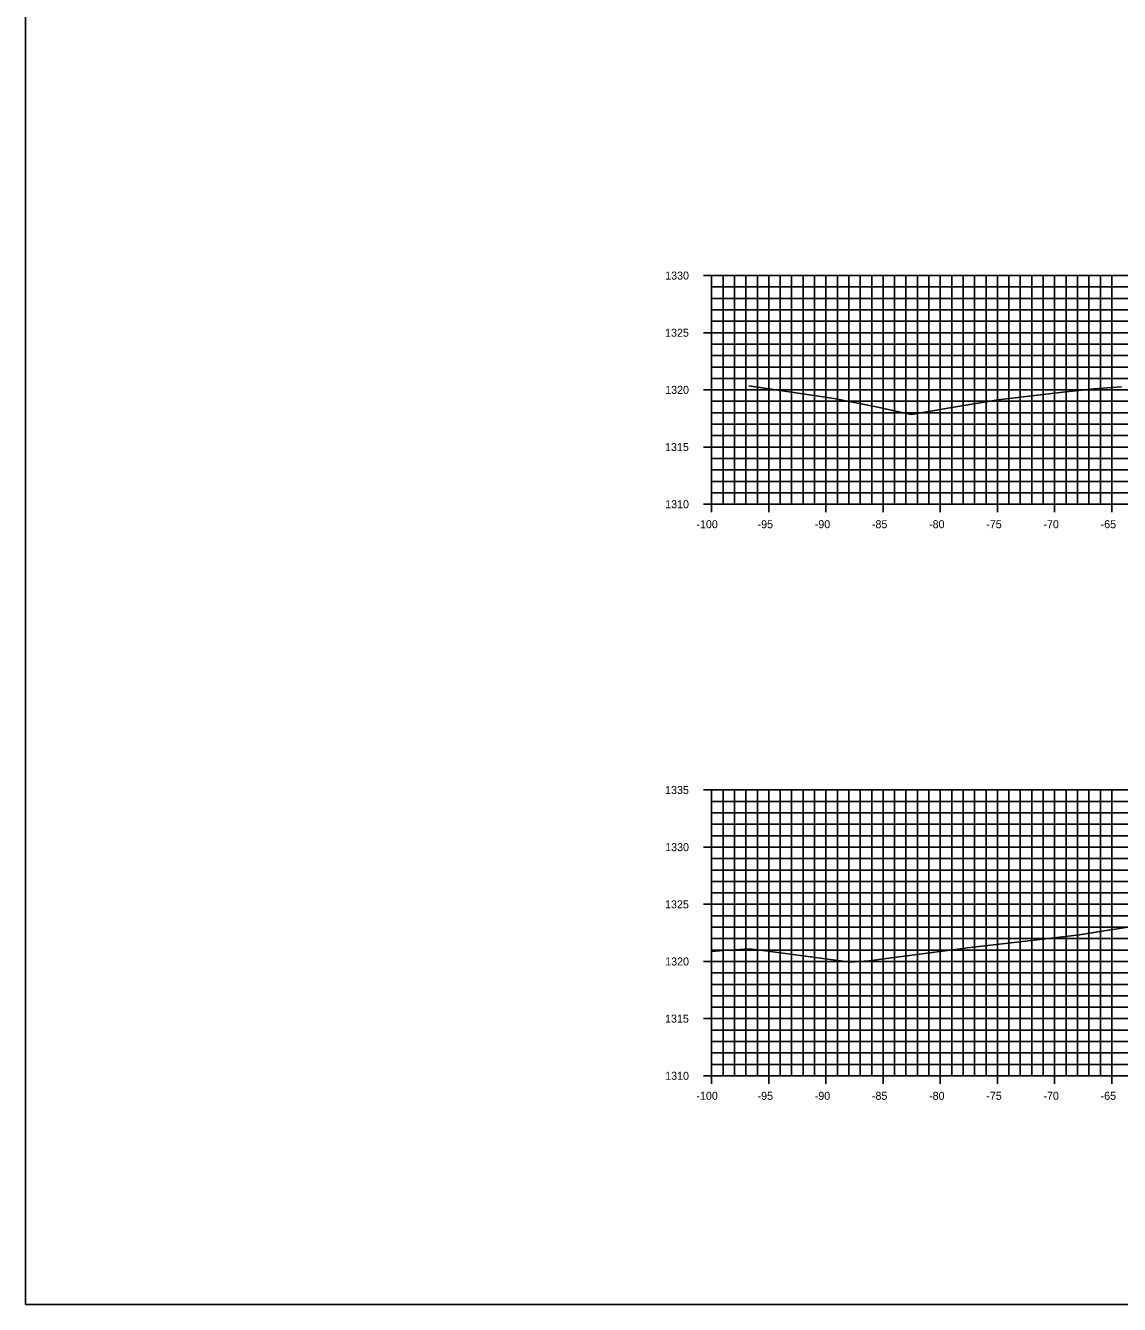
# Model space of a CAD drawing. Extents: x 674939 to 678919, y 750652 to 765176.
# Drawn here: x 678578.5 to 678674.2, y 753452.6 to 753564.4 of the extents above; entities that cross this region are included whole.
import ezdxf

# ---------------------------------------------------------------- set-up
doc = ezdxf.new("R2010")
doc.units = 0
for name, color, linetype in [('Level 10', 7, 'Continuous'), ('Level 20', 7, 'Continuous'), ('Level 4', 7, 'Continuous'), ('Level 8', 7, 'Continuous'), ('Level 9', 7, 'Continuous')]:
    doc.layers.add(name, color=color, linetype=linetype)

msp = doc.modelspace()

# ---------------------------------------------------------------- linework, layer by layer
at = {"layer": 'Level 10'}
for points in [[(678641.8, 753532.89), (678645.11, 753532.41), (678649.24, 753531.79), (678652.91, 753531.07), (678655.97, 753530.4), (678659.53, 753531.01), (678663.59, 753531.69), (678669.25, 753532.35), (678670.65, 753532.51), (678671.95, 753532.63), (678674.38, 753532.83)], [(678638.53, 753483.43), (678639.56, 753483.51), (678640.2, 753483.55), (678641.78, 753483.67), (678643.23, 753483.47), (678650.67, 753482.49), (678651.05, 753482.51), (678652.29, 753482.6), (678658.5, 753483.42), (678659.85, 753483.6), (678660.9, 753483.73), (678668, 753484.57), (678670.7, 753484.89), (678672.65, 753485.19), (678674.96, 753485.54)]]:
    msp.add_lwpolyline(points, dxfattribs=at)
at = {"layer": 'Level 20'}
for p, q in [((678638.53, 753542.55), (678838.53, 753542.55)), ((678638.53, 753522.55), (678638.53, 753542.55)), ((678639.53, 753522.55), (678639.53, 753542.55)), ((678640.53, 753522.55), (678640.53, 753542.55)), ((678641.53, 753522.55), (678641.53, 753542.55)), ((678642.53, 753522.55), (678642.53, 753542.55)), ((678643.53, 753522.55), (678643.53, 753542.55)), ((678644.53, 753522.55), (678644.53, 753542.55)), ((678645.53, 753522.55), (678645.53, 753542.55)), ((678646.53, 753522.55), (678646.53, 753542.55)), ((678647.53, 753522.55), (678647.53, 753542.55)), ((678648.53, 753522.55), (678648.53, 753542.55)), ((678649.53, 753522.55), (678649.53, 753542.55)), ((678650.53, 753522.55), (678650.53, 753542.55)), ((678651.53, 753522.55), (678651.53, 753542.55)), ((678652.53, 753522.55), (678652.53, 753542.55)), ((678653.53, 753522.55), (678653.53, 753542.55)), ((678654.53, 753522.55), (678654.53, 753542.55)), ((678655.53, 753522.55), (678655.53, 753542.55)), ((678656.53, 753522.55), (678656.53, 753542.55)), ((678657.53, 753522.55), (678657.53, 753542.55)), ((678658.53, 753522.55), (678658.53, 753542.55)), ((678659.53, 753522.55), (678659.53, 753542.55)), ((678660.53, 753522.55), (678660.53, 753542.55)), ((678661.53, 753522.55), (678661.53, 753542.55)), ((678662.53, 753522.55), (678662.53, 753542.55)), ((678663.53, 753522.55), (678663.53, 753542.55)), ((678664.53, 753522.55), (678664.53, 753542.55)), ((678665.53, 753522.55), (678665.53, 753542.55)), ((678666.53, 753522.55), (678666.53, 753542.55)), ((678667.53, 753522.55), (678667.53, 753542.55)), ((678668.53, 753522.55), (678668.53, 753542.55)), ((678669.53, 753522.55), (678669.53, 753542.55)), ((678670.53, 753522.55), (678670.53, 753542.55)), ((678671.53, 753522.55), (678671.53, 753542.55)), ((678672.53, 753522.55), (678672.53, 753542.55)), ((678673.53, 753522.55), (678673.53, 753542.55)), ((678638.53, 753541.55), (678838.53, 753541.55)), ((678638.53, 753540.55), (678838.53, 753540.55)), ((678638.53, 753539.55), (678838.53, 753539.55)), ((678638.53, 753538.55), (678838.53, 753538.55)), ((678638.53, 753537.55), (678838.53, 753537.55)), ((678638.53, 753536.55), (678838.53, 753536.55)), ((678638.53, 753535.55), (678838.53, 753535.55)), ((678638.53, 753534.55), (678838.53, 753534.55)), ((678638.53, 753533.55), (678838.53, 753533.55)), ((678638.53, 753532.55), (678838.53, 753532.55)), ((678638.53, 753531.55), (678838.53, 753531.55)), ((678638.53, 753530.55), (678838.53, 753530.55)), ((678638.53, 753529.55), (678838.53, 753529.55)), ((678638.53, 753528.55), (678838.53, 753528.55)), ((678638.53, 753527.55), (678838.53, 753527.55)), ((678638.53, 753526.55), (678838.53, 753526.55)), ((678638.53, 753525.55), (678838.53, 753525.55)), ((678638.53, 753524.55), (678838.53, 753524.55)), ((678638.53, 753523.55), (678838.53, 753523.55)), ((678638.53, 753522.55), (678838.53, 753522.55)), ((678638.53, 753497.55), (678838.53, 753497.55)), ((678638.53, 753472.55), (678638.53, 753497.55)), ((678639.53, 753472.55), (678639.53, 753497.55)), ((678640.53, 753472.55), (678640.53, 753497.55)), ((678641.53, 753472.55), (678641.53, 753497.55)), ((678642.53, 753472.55), (678642.53, 753497.55)), ((678643.53, 753472.55), (678643.53, 753497.55)), ((678644.53, 753472.55), (678644.53, 753497.55)), ((678645.53, 753472.55), (678645.53, 753497.55)), ((678646.53, 753472.55), (678646.53, 753497.55)), ((678647.53, 753472.55), (678647.53, 753497.55)), ((678648.53, 753472.55), (678648.53, 753497.55)), ((678649.53, 753472.55), (678649.53, 753497.55)), ((678650.53, 753472.55), (678650.53, 753497.55)), ((678651.53, 753472.55), (678651.53, 753497.55)), ((678652.53, 753472.55), (678652.53, 753497.55)), ((678653.53, 753472.55), (678653.53, 753497.55)), ((678654.53, 753472.55), (678654.53, 753497.55)), ((678655.53, 753472.55), (678655.53, 753497.55)), ((678656.53, 753472.55), (678656.53, 753497.55)), ((678657.53, 753472.55), (678657.53, 753497.55)), ((678658.53, 753472.55), (678658.53, 753497.55)), ((678659.53, 753472.55), (678659.53, 753497.55)), ((678660.53, 753472.55), (678660.53, 753497.55)), ((678661.53, 753472.55), (678661.53, 753497.55)), ((678662.53, 753472.55), (678662.53, 753497.55)), ((678663.53, 753472.55), (678663.53, 753497.55)), ((678664.53, 753472.55), (678664.53, 753497.55)), ((678665.53, 753472.55), (678665.53, 753497.55)), ((678666.53, 753472.55), (678666.53, 753497.55)), ((678667.53, 753472.55), (678667.53, 753497.55)), ((678668.53, 753472.55), (678668.53, 753497.55)), ((678669.53, 753472.55), (678669.53, 753497.55)), ((678670.53, 753472.55), (678670.53, 753497.55)), ((678671.53, 753472.55), (678671.53, 753497.55)), ((678672.53, 753472.55), (678672.53, 753497.55)), ((678673.53, 753472.55), (678673.53, 753497.55)), ((678638.53, 753496.55), (678838.53, 753496.55)), ((678638.53, 753495.55), (678838.53, 753495.55)), ((678638.53, 753494.55), (678838.53, 753494.55)), ((678638.53, 753493.55), (678838.53, 753493.55)), ((678638.53, 753492.55), (678838.53, 753492.55)), ((678638.53, 753491.55), (678838.53, 753491.55)), ((678638.53, 753490.55), (678838.53, 753490.55)), ((678638.53, 753489.55), (678838.53, 753489.55)), ((678638.53, 753488.55), (678838.53, 753488.55)), ((678638.53, 753487.55), (678838.53, 753487.55)), ((678638.53, 753486.55), (678838.53, 753486.55)), ((678638.53, 753485.55), (678838.53, 753485.55)), ((678638.53, 753484.55), (678838.53, 753484.55)), ((678638.53, 753483.55), (678838.53, 753483.55)), ((678638.53, 753482.55), (678838.53, 753482.55)), ((678638.53, 753481.55), (678838.53, 753481.55)), ((678638.53, 753480.55), (678838.53, 753480.55)), ((678638.53, 753479.55), (678838.53, 753479.55)), ((678638.53, 753478.55), (678838.53, 753478.55)), ((678638.53, 753477.55), (678838.53, 753477.55)), ((678638.53, 753476.55), (678838.53, 753476.55)), ((678638.53, 753475.55), (678838.53, 753475.55)), ((678638.53, 753474.55), (678838.53, 753474.55)), ((678638.53, 753473.55), (678838.53, 753473.55)), ((678638.53, 753472.55), (678838.53, 753472.55))]:
    msp.add_line(p, q, dxfattribs=at)
at = {"layer": 'Level 4'}
msp.add_lwpolyline([(678578.53, 753452.55), (678918.53, 753452.55), (678918.53, 753672.55), (678578.53, 753672.55)], close=True, dxfattribs=at)
at = {"layer": 'Level 8'}
for p, q in [((678637.83, 753542.55), (678639.23, 753542.55)), ((678638.53, 753522.55), (678638.53, 753542.55)), ((678638.53, 753541.55), (678638.88, 753541.55)), ((678638.53, 753540.55), (678638.88, 753540.55)), ((678638.53, 753539.55), (678638.88, 753539.55)), ((678638.53, 753538.55), (678638.88, 753538.55)), ((678637.83, 753537.55), (678639.23, 753537.55)), ((678638.53, 753536.55), (678638.88, 753536.55)), ((678638.53, 753535.55), (678638.88, 753535.55)), ((678638.53, 753534.55), (678638.88, 753534.55)), ((678638.53, 753533.55), (678638.88, 753533.55)), ((678637.83, 753532.55), (678639.23, 753532.55)), ((678638.53, 753531.55), (678638.88, 753531.55)), ((678638.53, 753530.55), (678638.88, 753530.55)), ((678638.53, 753529.55), (678638.88, 753529.55)), ((678638.53, 753528.55), (678638.88, 753528.55)), ((678637.83, 753527.55), (678639.23, 753527.55)), ((678638.53, 753526.55), (678638.88, 753526.55)), ((678638.53, 753525.55), (678638.88, 753525.55)), ((678638.53, 753524.55), (678638.88, 753524.55)), ((678638.53, 753523.55), (678638.88, 753523.55)), ((678638.53, 753521.85), (678638.53, 753523.25)), ((678643.53, 753521.85), (678643.53, 753523.25)), ((678648.53, 753521.85), (678648.53, 753523.25)), ((678653.53, 753521.85), (678653.53, 753523.25)), ((678658.53, 753521.85), (678658.53, 753523.25)), ((678663.53, 753521.85), (678663.53, 753523.25)), ((678668.53, 753521.85), (678668.53, 753523.25)), ((678673.53, 753521.85), (678673.53, 753523.25)), ((678637.83, 753522.55), (678639.23, 753522.55)), ((678638.53, 753522.55), (678838.53, 753522.55)), ((678637.83, 753497.55), (678639.23, 753497.55)), ((678638.53, 753472.55), (678638.53, 753497.55)), ((678638.53, 753496.55), (678638.88, 753496.55)), ((678638.53, 753495.55), (678638.88, 753495.55)), ((678638.53, 753494.55), (678638.88, 753494.55)), ((678638.53, 753493.55), (678638.88, 753493.55)), ((678637.83, 753492.55), (678639.23, 753492.55)), ((678638.53, 753491.55), (678638.88, 753491.55)), ((678638.53, 753490.55), (678638.88, 753490.55)), ((678638.53, 753489.55), (678638.88, 753489.55)), ((678638.53, 753488.55), (678638.88, 753488.55)), ((678637.83, 753487.55), (678639.23, 753487.55)), ((678638.53, 753486.55), (678638.88, 753486.55)), ((678638.53, 753485.55), (678638.88, 753485.55)), ((678638.53, 753484.55), (678638.88, 753484.55)), ((678637.83, 753482.55), (678639.23, 753482.55)), ((678638.53, 753483.55), (678638.88, 753483.55)), ((678638.53, 753481.55), (678638.88, 753481.55)), ((678638.53, 753480.55), (678638.88, 753480.55)), ((678638.53, 753479.55), (678638.88, 753479.55)), ((678638.53, 753478.55), (678638.88, 753478.55)), ((678637.83, 753477.55), (678639.23, 753477.55)), ((678638.53, 753476.55), (678638.88, 753476.55)), ((678638.53, 753475.55), (678638.88, 753475.55)), ((678638.53, 753474.55), (678638.88, 753474.55)), ((678637.83, 753472.55), (678639.23, 753472.55)), ((678638.53, 753473.55), (678638.88, 753473.55)), ((678638.53, 753471.85), (678638.53, 753473.25)), ((678638.53, 753472.55), (678838.53, 753472.55)), ((678643.53, 753471.85), (678643.53, 753473.25)), ((678648.53, 753471.85), (678648.53, 753473.25)), ((678653.53, 753471.85), (678653.53, 753473.25)), ((678658.53, 753471.85), (678658.53, 753473.25)), ((678663.53, 753471.85), (678663.53, 753473.25)), ((678668.53, 753471.85), (678668.53, 753473.25)), ((678673.53, 753471.85), (678673.53, 753473.25))]:
    msp.add_line(p, q, dxfattribs=at)

# ---------------------------------------------------------------- texts
at = {"layer": 'Level 9'}
for s, p in [('1330', (678634.47, 753542.2)), ('1325', (678634.46, 753537.2)), ('1320', (678634.47, 753532.2)), ('1315', (678634.46, 753527.2)), ('1310', (678634.47, 753522.2)), ('-100', (678637.2, 753520.45)), ('-95', (678642.55, 753520.45)), ('-90', (678647.55, 753520.45)), ('-85', (678652.55, 753520.45)), ('-80', (678657.55, 753520.45)), ('-75', (678662.55, 753520.45)), ('-70', (678667.55, 753520.45)), ('-65', (678672.55, 753520.45)), ('1335', (678634.46, 753497.2)), ('1330', (678634.47, 753492.2)), ('1325', (678634.46, 753487.2)), ('1320', (678634.47, 753482.2)), ('1315', (678634.46, 753477.2)), ('1310', (678634.47, 753472.2)), ('-100', (678637.2, 753470.45)), ('-95', (678642.55, 753470.45)), ('-90', (678647.55, 753470.45)), ('-85', (678652.55, 753470.45)), ('-80', (678657.55, 753470.45)), ('-75', (678662.55, 753470.45)), ('-70', (678667.55, 753470.45)), ('-65', (678672.55, 753470.45))]:
    msp.add_text(s, height=0.7, dxfattribs=at).set_placement(p)

doc.saveas('drawing.dxf')
